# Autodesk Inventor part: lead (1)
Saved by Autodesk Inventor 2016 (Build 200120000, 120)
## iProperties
Created: 2016-09
Part Number: lead (1)
Material: Generic
Document SubType Name: Modeling
Designer: Administrator
Appearance: Generic
Author: Administrator
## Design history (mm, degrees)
feature "Body1"
feature "Body2"
feature "Body3"
feature "Body4"
feature "Body5"
body "Solid1"
body "Solid2"
body "Solid3"
body "Solid4"
body "Solid5"
